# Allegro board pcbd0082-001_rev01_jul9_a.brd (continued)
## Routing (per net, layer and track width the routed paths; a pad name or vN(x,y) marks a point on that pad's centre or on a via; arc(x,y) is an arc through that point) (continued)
NFP_SERDES1_RX2_P: length 55.6
  TOP w0.099: U1.AH26 v2(47.9,52.28)
  07_SIG w0.096: v2(47.9,52.28) 47.9,52.25 47.74,52.09 47.56,52.09 47.51,52.15 47.51,53.62 47.24,53.89 41.47,53.89 41.34,54.01 41.24,54.01 40.81,54.44 38.02,54.44 37.87,54.29 36.82,53.24 33.6,53.24 33.45,53.08 32.34,51.97 30.23,51.97 28.51,50.25 27.64,50.25 27.17,49.77 27.17,47.11 26.85,46.79 26.85,46.25 26.31,45.71 26.11,45.71 26.1,45.7 25.76,45.7 23.8,43.75 23.8,43.58 23.69,43.46 23.69,42.4 21.17,39.87 19.9,39.87 18.99,38.96 18.99,37.73 18.62,37.36 9.78,37.36 9.26,36.84 9.26,35.95 9.62,35.58 10.68,35.58 10.81,35.46 10.85,35.46 v5(10.93,35.37)
  BOTTOM w0.099: J4.136 v5(10.93,35.37)
NFP_SERDES1_RX3_N: length 55
  TOP w0.099: U1.AH27 v8(46.9,52.28)
  07_SIG w0.096: v8(46.9,52.28) 46.5,52.68 46.15,52.68 46.15,52.68 41.44,52.68 41.31,52.81 40.63,52.81 40.53,52.91 38.25,52.91 37.07,51.73 34.28,51.73 33.5,50.95 30.72,50.95 29.07,49.3 29.07,47.05 26.72,44.7 26.52,44.7 26.52,44.7 26.24,44.7 25.33,43.79 25.33,43.17 24.7,42.53 24.7,41.77 22.03,39.1 22.03,38.45 21.79,38.2 21.79,37.62 20.57,36.4 20.57,35.1 20.06,34.59 9.64,34.59 9.52,34.46 9.52,33.76 9.76,33.52 11.22,33.52 11.41,33.34 12.22,33.34 12.43,33.55 12.43,33.87 v5(12.2,34.1)
  BOTTOM w0.099: J4.143 v5(12.2,34.1)
NFP_SERDES1_RX3_P: length 55.1
  TOP w0.099: U1.AJ27 v2(46.9,53.28)
  07_SIG w0.096: v2(46.9,53.28) 46.51,52.89 46.07,52.89 46.06,52.89 41.53,52.89 41.4,53.02 40.78,53.02 40.64,53.17 38.15,53.17 36.97,51.99 34.17,51.99 33.39,51.21 30.61,51.21 28.81,49.41 28.81,47.16 26.62,44.96 26.42,44.96 26.41,44.96 26.14,44.96 25.07,43.89 25.07,43.28 24.44,42.64 24.44,41.87 21.77,39.21 21.77,38.56 21.53,38.31 21.53,37.73 20.31,36.51 20.31,35.2 19.95,34.85 9.54,34.85 9.26,34.57 9.26,33.65 9.65,33.26 11.11,33.26 11.3,33.08 12.1,33.08 12.2,32.97 v5(12.2,32.83)
  BOTTOM w0.099: J4.151 v5(12.2,32.83)
NFP_SERDES1_TX0_N: length 54.8
  TOP w0.099: U1.AK24 v8(49.9,54.28)
  08_SIG w0.096: v5(10.93,50.61) 11.4,51.07 14.07,51.07 14.32,51.32 14.32,52.25 14.41,52.34 16.35,52.34 16.76,52.75 16.76,54.65 16.99,54.88 20.03,54.88 20.52,55.37 20.52,60.45 20.67,60.6 48.52,60.6 49.27,59.85 49.27,57.24 49.29,57.21 49.29,54.89 v8(49.9,54.28)
  BOTTOM w0.099: J4.40 v5(10.93,50.61)
NFP_SERDES1_TX0_P: length 54.9
  TOP w0.099: U1.AL24 v2(49.9,55.28)
  08_SIG w0.096: v5(10.93,51.88) 11.48,51.33 13.96,51.33 14.06,51.43 14.06,52.35 14.3,52.6 16.24,52.6 16.5,52.86 16.5,54.76 16.88,55.14 19.93,55.14 20.26,55.48 20.26,60.56 20.56,60.86 48.63,60.86 49.53,59.96 49.53,57.24 49.51,57.21 49.51,55.11 49.61,55.01 49.79,55.01 49.9,55.11 v2(49.9,55.28)
  BOTTOM w0.099: J4.32 v5(10.93,51.88)
NFP_SERDES1_TX1_N: length 54.9
  TOP w0.099: U1.AL25 v8(48.9,55.28)
  08_SIG w0.096: v8(48.9,55.28) 48.29,55.89 48.29,57.26 48.27,57.29 48.27,59.07 47.49,59.85 21.37,59.85 21.27,59.75 21.27,55.34 21.32,55.3 21.32,52.76 20.87,52.31 18.23,52.31 18.03,52.11 18.03,50.02 17.78,49.77 17.1,49.77 16.85,49.52 16.85,48.9 16.52,48.57 15.54,48.57 15.33,48.57 15.07,48.83 15.07,49.82 14.97,49.92 14.68,49.92 14.58,49.82 14.58,48.83 14.32,48.57 12.71,48.57 v5(12.2,48.07)
  BOTTOM w0.099: J4.55 v5(12.2,48.07)
NFP_SERDES1_TX1_P: length 54.9
  TOP w0.099: U1.AM25 v2(48.9,56.28)
  08_SIG w0.096: v5(12.2,49.34) 12.71,48.83 14.21,48.83 14.32,48.94 14.32,49.93 14.57,50.18 15.08,50.18 15.33,49.93 15.33,48.94 15.43,48.83 16.41,48.83 16.59,49.01 16.59,49.63 17,50.03 17.67,50.03 17.77,50.13 17.77,52.22 18.12,52.57 20.76,52.57 21.06,52.87 21.06,55.19 21.01,55.24 21.01,59.86 21.26,60.11 47.59,60.11 48.53,59.17 48.53,57.27 48.51,57.25 48.51,56.13 48.61,56.03 48.79,56.03 48.9,56.14 v2(48.9,56.28)
  BOTTOM w0.099: J4.47 v5(12.2,49.34)
NFP_SERDES1_TX2_N: length 54.8
  TOP w0.099: U1.AK26 v8(47.9,54.28)
  08_SIG w0.096: v8(47.9,54.28) 47.29,54.89 47.29,57.08 47.27,57.1 47.27,58.45 46.62,59.1 22.87,59.1 22.74,58.97 22.74,58.63 22.49,58.39 22.19,58.39 22.09,58.29 22.09,58 22.19,57.91 22.49,57.91 22.74,57.66 22.74,53.14 20.73,51.14 20.73,50.54 20.11,49.91 19.79,49.91 19.25,49.38 19.25,49.05 18.84,48.64 18.45,48.64 17.98,48.18 17.98,47.78 17.57,47.37 15.7,47.37 15.58,47.25 15.58,45.08 15.23,44.73 14.21,44.73 13.91,45.03 13.91,45.79 13.7,45.99 12.67,45.99 v5(12.2,45.53)
  BOTTOM w0.099: J4.72 v5(12.2,45.53)
NFP_SERDES1_TX2_P: length 54.8
  TOP w0.099: U1.AL26 v2(47.9,55.28)
  08_SIG w0.096: v2(47.9,55.28) 47.9,55.15 47.76,55.01 47.61,55.01 47.51,55.11 47.51,57.08 47.53,57.1 47.53,58.55 46.72,59.36 22.76,59.36 22.48,59.08 22.48,58.74 22.39,58.65 22.08,58.65 21.83,58.4 21.83,57.9 22.08,57.65 22.39,57.65 22.48,57.55 22.48,53.25 20.47,51.25 20.47,50.64 20,50.17 19.68,50.17 18.99,49.48 18.99,49.16 18.73,48.9 18.34,48.9 17.72,48.28 17.72,47.89 17.46,47.63 15.59,47.63 15.32,47.36 15.32,45.19 15.12,44.99 14.32,44.99 14.17,45.14 14.17,45.89 13.81,46.25 12.75,46.25 v5(12.2,46.8)
  BOTTOM w0.099: J4.64 v5(12.2,46.8)
NFP_SERDES1_TX3_N: length 55.3
  TOP w0.099: U1.AL27 v8(46.9,55.28)
  08_SIG w0.096: v8(46.9,55.28) 46.29,55.89 46.29,56.45 46.2,56.54 46.2,57.09 46.18,57.11 46.18,57.86 45.73,58.31 24.24,58.31 23.54,57.61 23.54,56.48 23.65,56.38 25.02,56.38 25.28,56.12 25.28,55.63 25.02,55.37 24.68,55.37 23.65,55.37 23.54,55.26 23.54,54.55 23.65,54.44 24.11,54.44 24.37,54.18 24.37,53.69 24.11,53.43 23.65,53.43 23.54,53.32 23.54,52.41 22.79,51.66 22.79,50.68 20.82,48.71 20.82,48.04 20.02,47.23 19.64,47.23 19.39,46.98 19.39,45.08 19,44.69 17.1,44.69 16.85,44.44 16.85,44.08 16.27,43.49 15.58,43.49 15.47,43.39 15.47,43.21 15.21,42.95 14.72,42.95 14.47,43.21 14.47,43.39 14.36,43.49 12.71,43.49 v5(12.2,42.99)
  BOTTOM w0.099: J4.87 v5(12.2,42.99)
NFP_SERDES1_TX3_P: length 55.2
  TOP w0.099: U1.AM27 v2(46.9,56.28)
  08_SIG w0.096: v5(12.2,44.26) 12.71,43.75 14.47,43.75 14.73,43.49 14.73,43.32 14.83,43.21 15.11,43.21 15.21,43.32 15.21,43.49 15.47,43.75 16.16,43.75 16.59,44.19 16.59,44.55 17,44.95 18.89,44.95 19.13,45.19 19.13,47.09 19.54,47.49 19.91,47.49 20.56,48.14 20.56,48.82 22.53,50.79 22.53,51.77 23.28,52.52 23.28,53.43 23.54,53.69 24,53.69 24.11,53.8 24.11,54.07 24,54.18 23.54,54.18 23.28,54.44 23.28,55.37 23.54,55.63 24.57,55.63 24.92,55.63 25.02,55.73 25.02,56.01 24.92,56.12 23.54,56.12 23.28,56.37 23.28,57.72 24.13,58.57 45.83,58.57 46.44,57.97 46.44,57.11 46.41,57.09 46.41,56.63 46.51,56.53 46.51,56.12 46.6,56.03 46.74,56.03 46.9,56.19 v2(46.9,56.28)
  BOTTOM w0.099: J4.79 v5(12.2,44.26)
NFP_SERDES012_SYSCLK_IN_N: length 13.1
  TOP w0.099: U1.AE26 v2(47.9,49.28) ; R132.2 v7(40.25,51.33)
  04_SIG w0.096: v7(40.25,51.33) 40.25,51.73 40.49,51.98 41.35,51.98 41.65,51.68 45.06,51.68 45.29,51.44 45.29,49.97 45.58,49.68 48.15,49.68 48.25,49.58 48.25,49.4 48.15,49.3 47.92,49.3 v2(47.9,49.28)
  BOTTOM w0.099: v2(47.9,49.28) R322.2
NFP_SERDES012_SYSCLK_IN_P: length 13
  TOP w0.099: U1.AE25 v2(48.9,49.28) ; R133.2 v7(40.25,52.47)
  04_SIG w0.096: v7(40.25,52.47) 40.53,52.19 41.44,52.19 41.74,51.89 45.15,51.89 45.5,51.53 45.5,50.05 45.67,49.89 48.29,49.89 v2(48.9,49.28)
  BOTTOM w0.099: v2(48.9,49.28) R319.2
NFP_SMBUS_ALERT_L: length 12.6
  TOP w0.147: R391.1 21.07,51.29 21.07,50.32 22.72,48.66 24.5,48.66 24.75,48.92 24.75,51.59 25.26,52.09 v4(25.26,52.47) 25.26,53.11 25.26,53.11 U20.4
  BOTTOM w0.147: R379.1 25.26,53.83 v4(25.26,52.47)
NFP_SMBUS_SCL: length 15.5
  TOP w0.147: v4(27.39,57.43) 27.22,57.25 U20.9 ; R389.1 v5(17.51,58.57)
  07_SIG w0.121: v5(17.51,58.57) 17.51,58.85 18.24,59.57 20.07,59.57 20.13,59.51 23.88,59.51 24.06,59.33 25.49,59.33 v4(27.39,57.43)
  BOTTOM w0.147: R370.1 27.39,56.55 v4(27.39,57.43)
NFP_SMBUS_SDA: length 5.9
  TOP w0.147: U20.7 26.76,52.95 R382.1 v4(27.39,52.47) 28.05,52.47 29.32,51.2 R351.1
  BOTTOM w0.147: v4(27.39,52.47) 27.39,53.35 R369.1
NFP_SPI2_CS: length 16.5
  TOP w0.127: v3(32.63,38.56) 32.21,38.09 32.21,37.54 32.32,37.43 32.32,37.42 32.91,36.83 U2.P11
  TOP w0.132: U1.W31 v2(42.9,43.28)
  TOP w0.147: v3(32.63,38.56) v1(32.63,39.39)
  03_SIG w0.121: v2(42.9,43.28) 42.9,42.94 42.31,42.35 42.31,41.97 42.02,41.68 40.63,41.68 37.96,39.01 33.01,39.01 32.63,38.63 v3(32.63,38.56)
NFP_SPI2_MISO: length 11.8
  TOP w0.132: U1.V31 v8(42.9,42.28)
  02_GND w0.127: U2.N4 35.98,36.71 v3(35.98,37.72)
  03_SIG w0.121: v3(35.98,37.72) 35.98,37.7 35.99,37.69 36.13,37.69 36.56,38.12 37.96,38.12 38.23,38.39 38.23,38.51 38.47,38.76 39.74,38.76 40.11,39.13 40.74,39.13 42.41,40.79 42.41,41.43 42.9,41.92 v8(42.9,42.28)
NFP_SPI2_MOSI: length 16.3
  TOP w0.127: U2.P13 31.37,37.32 31.37,38.06 v3(31.81,38.56)
  07_SIG w0.121: v3(31.81,38.56) 32.65,39.39 39.61,39.39 40.21,39.99 43.46,39.99 43.9,39.55 v2(43.9,39.28)
  BOTTOM w0.147: R203.2 43.98,39.36 v2(43.9,39.28)
NFP_SPI2_SCK: length 13.1
  TOP w0.127: U2.M4 36.36,35.78 36.04,35.46 35.78,35.46 v3(35.5,35.18)
  07_SIG w0.121: v3(35.5,35.18) 35.83,35.18 36.19,34.81 38.31,34.81 38.43,34.68 39.62,34.68 40.5,33.81 45.38,33.81 v2(45.9,33.28)
  BOTTOM w0.147: R199.2 v2(45.9,33.28)
NFP_SRESET_L: length 17.9
  TOP w0.132: U1.M29 v2(44.9,35.28)
  02_GND w0.127: U2.N13 31.91,37.6 v3(31.79,37.72)
  07_SIG w0.121: v2(44.9,35.28) 44.87,35.28 44.44,35.71 43.9,35.71 43.5,36.12 43.5,36.27 43.04,36.73 41.52,36.73 41.07,36.28 33.23,36.28 v3(31.79,37.72)
  BOTTOM w0.127: R57.1 30.98,36.9 v3(31.79,37.72)
NFP_UART_SR_RX: length 52.2
  TOP w0.132: U1.N31 v2(42.9,36.28)
  04_SIG w0.121: v4(48.25,12.6) 47.61,11.96 46.08,11.96 46.02,12.02 44.61,12.02 44.17,11.58 43.17,11.58 42.53,12.22 39.61,12.22 38.85,12.98 38.85,13.74 38.09,14.5 34.33,14.5 33.19,13.36 30.92,13.36 30.66,13.62 30.66,13.85 30.01,14.5 28.81,14.5 v4(28.56,14.25)
  08_SIG w0.121: v4(48.25,12.6) 47.49,13.36 43.8,13.36 42.85,14.31 42.85,22.95 43.42,23.52 43.42,35.76 v2(42.9,36.28)
NFP_UART_SR_TX: length 45.8
  07_SIG w0.121: v5(28.56,12.91) 28.56,12.85 29.58,11.83 31.11,11.83 32.32,10.63 32.68,10.63 33.3,11.25 35.42,11.25 35.8,11.63 37.02,11.63 37.65,11.01 38.52,11.01 38.89,10.64 38.9,10.63 40.05,10.63 40.67,10 41.71,10 41.97,9.74 42.85,9.74 43.75,10.64 45.52,10.64 46.34,11.46 v4(46.34,12.6)
  08_SIG w0.121: v5(28.56,12.91) 28.5,12.98 27.55,12.98 26.78,13.74 26.78,18.24 27.93,19.38 27.93,21.06 28.3,21.43 28.3,23.79 28.18,23.91 28.18,27.21 28.24,27.27 28.24,27.64 28.05,27.83 28.05,29.23 27.55,29.74 26.59,29.74 v4(25.78,30.55)
  BOTTOM w0.147: v4(25.78,30.55) 26.11,30.88 R200.2 ; J5.26 v5(28.56,12.91)
NFP_VDD_CORE_IMON: length 4.2
  TOP w0.147: U10.8 29.98,19.47 29.83,19.33 v4(29.49,19.33) C125.2
  BOTTOM w0.147: v4(29.49,19.33) 28.94,19.33 TP38.1
NFP_VDD_CORE_ISEN1_N: length 34.3
  07_SIG w0.254: v4(39.9,20.71) 40.23,20.71 41.26,21.74 44.52,21.74 45.66,22.88 47,22.88 47.94,23.81 58,23.81 58.38,23.43 68.19,23.43 68.44,23.18 68.44,22.56 68.75,22.25 69.2,22.25 69.46,21.99 69.46,21.74 69.2,21.49 68.2,21.49 67.77,21.92 v4(67.77,21.99)
NFP_VDD_CORE_ISEN1_P: length 37
  TOP w0.254: v5(70.54,22.57) 70.47,22.5 70.47,22.38 70.38,22.29 R171.2 ; v4(39.9,19.7) R325.2
  07_SIG w0.254: v4(39.9,19.7) 39.4,20.29 39.4,20.92 39.69,21.22 40.2,21.22 41.1,22.12 44.36,22.12 45.5,23.26 46.85,23.26 47.43,23.84 47.43,24.48 47.7,24.75 48.72,24.75 48.76,24.79 57.56,24.79 58.53,23.81 68.4,23.81 68.69,23.52 69.58,23.52 v5(70.54,22.57)
NFP_VDD_CORE_ISEN2_N: length 22.8
  07_SIG w0.254: v4(57.18,21.87) 55.28,21.87 54.13,23.01 50.63,23.01 49.61,21.99 47.11,21.99 46.9,21.78 46.73,21.78 46.35,21.4 46.32,21.4 45.9,20.98 44.02,20.98 43.52,20.48 41.71,20.48 38.98,17.74 38.98,17.01 39.4,16.58 39.59,16.58 v4(39.88,16.28)
NFP_VDD_CORE_ISEN2_P: length 19.6
  TOP w0.254: v4(39.88,17.17) R324.2
  07_SIG w0.254: v4(54.56,21.87) 53.84,22.59 53.84,22.63 50.79,22.63 49.77,21.61 47.27,21.61 47.05,21.4 46.89,21.4 46.51,21.02 46.47,21.02 46.06,20.6 44.18,20.6 43.68,20.1 41.87,20.1 39.36,17.58 39.36,17.17 39.56,16.97 39.67,16.97 v4(39.88,17.17)
NFP_VDD_CORE_SENSE_VDD: length 52.9
  TOP w0.254: R313.2 v5(34.53,13.1) ; v5(34.53,13.1) v1(35.07,12.57) ; v5(34.53,13.1) R182.2 ; U1.AC25 v2(48.9,47.28)
  07_SIG w0.254: v2(48.9,47.28) 48.37,46.75 48.37,27.96 48.13,27.72 48.09,27.75 47.7,27.75 47.66,27.71 47.1,27.71 46.72,27.33 46.72,26.44 46.04,25.75 41.7,25.75 41.43,25.48 41.43,25.43 41.04,25.04 39.48,25.04 38.6,24.16 38.28,24.16 38.22,24.11 36.9,24.11 36.11,23.32 36.11,19.22 35.43,18.55 34.23,18.55 32.81,17.13 32.81,17.11 v5(32.44,16.74)
  BOTTOM w0.254: v2(48.9,47.28) 49.4,47.78 R286.1 ; v5(34.53,13.1) 33.39,13.1 31.99,14.5 31.99,16.29 v5(32.44,16.74)
NFP_VDD_CORE_SENSE_VSS: length 53.2
  TOP w0.254: U10.13 33.03,17.08 33.19,16.91 v5(33.31,16.91) ; C125.1 R323.2 28.65,18.57 v4(28.44,18.35) ; U1.AC24 v2(49.9,47.28)
  07_SIG w0.254: v5(33.31,16.91) 33.27,16.93 33.4,16.93 34.64,18.17 35.59,18.17 36.49,19.07 36.49,23.16 37.06,23.73 38.38,23.73 38.43,23.78 38.86,23.78 39.17,24.09 39.17,24.11 39.46,24.41 39.48,24.41 39.74,24.66 41.26,24.66 41.41,24.81 43.09,24.81 43.65,25.37 46.19,25.37 47.63,26.81 48.09,26.81 48.37,27.09 48.37,27.42 48.76,27.81 49.09,27.81 49.39,28.11 49.39,46.76 49.9,47.27 v2(49.9,47.28)
  BOTTOM w0.254: v4(28.44,18.35) 28.44,17.74 29.13,17.04 30.88,17.04 31.08,17.24 31.51,17.24 31.56,17.3 32.93,17.3 v5(33.31,16.91) ; v2(49.9,47.28) R285.2
NFP_VDD_CORE_TCOMPA: length 35.5
  TOP w0.147: v4(38.98,15.35) R327.2 38.05,15.39 C34.2 C35.2 36.73,16.79 36.02,16.79 35.53,17.28 U10.18
  04_SIG w0.121: v4(65.18,12.47) 64.62,12.47 64.5,12.35 64.5,12.13 64.5,12.12 64.5,11.48 64.1,11.08 62.31,11.08 62.12,10.89 60.03,10.89 58.19,12.73 49.14,12.73 48.71,13.17 45.86,13.17 45.43,12.73 40.54,12.73 39.44,13.82 39.44,14.8 39.44,14.92 v4(38.98,15.35)
NFP_VDD_CORE_TCOMPB: length 32.8
  TOP w0.147: v4(40.12,15.39) 40.12,14.88 39.65,14.41 R329.2 38.89,14.5 R13.1
  04_SIG w0.121: v4(40.12,15.39) 39.69,14.93 39.69,14.81 39.69,13.93 40.64,12.98 45.33,12.98 45.76,13.41 48.81,13.41 49.24,12.98 58.29,12.98 58.56,12.71 60.13,11.14 62.02,11.14 62.21,11.33 64,11.33 64.25,11.58 64.25,12.23 64.25,12.23 64.25,12.35 64.13,12.47 v4(63.58,12.47)
NWK0_I2C_SCL: length 17
  08_SIG w0.121: v5(10.93,31.56) 11.16,31.79 11.16,33.22 10.73,33.66 9.79,33.66 v7(6.72,36.73) 5.96,37.49 v4(5.96,42.7)
  BOTTOM w0.147: R377.1 5.96,41.97 v4(5.96,42.7) 5.96,43.33 5.95,43.33 U21.4
  BOTTOM w0.254: J4.160 v5(10.93,31.56)
NWK0_I2C_SDA: length 16.9
  08_SIG w0.121: v4(3.82,42.7) 5.19,41.32 v7(5.19,37.36) 5.19,37.18 9.55,32.83 10.62,32.83 v5(10.66,32.79)
  BOTTOM w0.147: R373.1 3.97,42 R386.1 4.45,43.17 U21.7
  BOTTOM w0.254: v5(10.66,32.79) 10.97,32.79 J4.152
NWK0_LED_ACT_G_L: length 39.8
  TOP w0.127: v3(34.51,32.76) 34.92,32.35 35.49,32.35 35.74,32.1 35.74,31.87 36.02,31.6 36.09,31.6 U2.C4
  03_SIG w0.121: v5(13.47,41.72) 13.96,41.24 13.96,35.33 14.39,34.89 23.66,34.89 24.75,33.81 24.75,30.96 25.6,30.11 25.65,30.11 25.9,29.87 28.04,29.87 28.52,30.35 28.66,30.35 29.69,31.38 29.69,31.4 29.92,31.63 29.94,31.63 29.96,31.65 32.63,31.65 33.3,32.32 34.06,32.32 v3(34.51,32.76)
  BOTTOM w0.147: v1(37.71,31.14) 37.26,31.59 36.01,31.59 35.76,31.84 35.76,32.09 35.09,32.76 v3(34.51,32.76)
  BOTTOM w0.254: J4.94 v5(13.47,41.72)
NWK0_LED_LINK_G_L: length 40.4
  02_GND w0.121: U2.B3 36.91,29.7 37.58,29.03 37.58,28.47 v3(37.71,28.34)
  03_SIG w0.121: v3(37.71,28.34) 37.71,28.9 35.82,30.79 29.87,30.79 29.11,30.03 29.11,29.76 28.86,29.52 25.87,29.52 25.51,29.87 25.13,29.87 24.3,30.7 24.3,33.75 23.42,34.63 22.54,34.63 22.45,34.54 13.22,34.54 12.94,34.82 12.94,39.39 13.47,39.93 v5(13.47,40.45)
  BOTTOM w0.254: J4.102 v5(13.47,40.45)
NWK0_MOD_PRES_L: length 25.1
  02_GND w0.121: v3(33.69,32.74) 34.11,32.32 34.11,31.56 34.4,31.27 34.42,31.27 U2.B7
  04_SIG w0.121: v3(33.69,32.74) 31.31,32.74 30.59,32.03 28.94,32.03 28.46,31.54 26.14,31.54 25.26,30.66 23.68,30.66 23.45,30.88 21.83,30.88 21.45,30.5 14.53,30.5 v5(13.47,31.56)
  BOTTOM w0.254: J4.158 v5(13.47,31.56)
NWK1_I2C_SCL: length 38
  08_SIG w0.121: v6(19.82,34.1) 20.43,33.49 20.43,30.76 19.93,30.25 11.42,30.25 3.29,38.38 3.29,43.84 3.82,44.37 v4(3.82,47.65)
  BOTTOM w0.147: R374.1 v4(3.82,47.65) 4,47.47 U21.9
  BOTTOM w0.254: J4.137 v6(19.82,34.1)
NWK1_I2C_SDA: length 35.9
  08_SIG w0.121: v4(5.96,47.65) 5.58,47.27 5.58,45.11 7.61,43.08 7.61,38.07 8.98,36.7 8.98,35.56 10,34.54 11.5,34.54 11.76,34.28 11.76,31.3 12.05,31.01 19.04,31.01 19.29,31.27 19.29,34.19 19.38,34.28 19.38,34.28 19.82,34.72 v6(19.82,35.37)
  BOTTOM w0.147: R378.1 5.61,48.5 5.96,48.16 v4(5.96,47.65) 5.45,47.14 U21.12
  BOTTOM w0.254: J4.129 v6(19.82,35.37)
NWK1_LED_ACT_G_L: length 31.4
  TOP w0.127: v3(30.95,29.08) 31.91,30.01 U2.A13
  08_SIG w0.121: v5(14.74,39.18) 14.8,39.18 14.8,39.12 15.35,38.57 15.35,37.74 15.63,37.47 20.2,37.47 21.14,36.53 21.14,35.39 21.45,35.08 22.28,35.08 22.33,35.12 23.11,35.12 23.16,35.08 24.24,35.08 26.21,37.04 28.18,37.04 28.63,37.49 29.58,37.49 30.02,37.04 30.28,37.04 31.1,36.22 31.1,29.87 30.98,29.74 v3(30.95,29.08)
  BOTTOM w0.147: v3(30.95,29.08) 30.95,29.59 v1(31.23,29.87)
  BOTTOM w0.254: J4.109 v5(14.74,39.18)
NWK1_LED_LINK_G_L: length 30.7
  TOP w0.147: v3(37.66,37.72) 37.68,37.72 38.09,38.12 38.09,38.63 38.34,38.89 v1(39.48,38.89)
  02_GND w0.127: v3(37.66,37.72) 37.66,37.02 U2.N3
  03_SIG w0.121: v3(37.66,37.72) 37.37,37.72 36.98,37.33 30.06,37.33 28.95,36.22 28.13,36.22 28.07,36.27 26.65,36.27 26.59,36.22 26.08,36.22 25.01,35.14 20.75,35.14 20.05,35.84 19.55,35.84 19.14,36.25 19.14,36.76 18.81,37.08 15.57,37.08 v5(14.74,37.91)
  BOTTOM w0.254: J4.117 v5(14.74,37.91)
NWK1_MOD_PRES_L: length 54.4
  02_GND w0.127: v3(30.09,30.4) 31.03,30.4 U2.C13
  08_SIG w0.121: v5(13.47,54.42) 13.47,54.41 12.69,53.62 10.53,53.62 10.33,53.42 10.33,39.13 11.67,37.8 11.67,37.49 11.93,37.23 12.81,37.23 12.98,37.07 12.98,35.16 13.27,34.87 13.45,34.69 16.12,34.69 16.84,35.42 16.84,35.55 18.4,37.11 20.05,37.11 20.82,36.35 20.82,35.2 21.32,34.69 22.25,34.69 22.43,34.88 23.01,34.88 23.19,34.69 24.5,34.69 26.4,36.6 30.21,36.6 30.85,35.96 30.85,31.16 v3(30.09,30.4)
  BOTTOM w0.148: J4.14 v5(13.47,54.42)
PCIE0_REFCLK_N: length 63.9
  TOP w0.099: v8(60.9,49.28) U1.AE14
  04_SIG w0.096: v8(60.9,49.28) 61.29,49.68 61.29,50.53 61.65,50.89 62.06,50.89 62.29,51.12 62.29,55.72 62.27,55.74 62.27,55.99 61.58,56.68 57.74,56.68 57.34,56.28 56.63,56.28 56.23,56.68 55.74,56.68 55.5,56.45 55.5,56.44 55.39,56.33 54.68,56.33 54.33,56.68 53.71,56.68 53.31,56.28 52.58,56.28 52.18,56.68 50.79,56.68 50.17,57.29 32.96,57.29 32.42,57.83 29.38,57.83 28.13,56.58 23.77,56.58 23.16,55.97 21.26,55.97 20.17,54.88 11.77,54.88 11.56,54.68 11.56,54.36 11.67,54.25 12.04,54.25 v5(12.2,54.42)
  BOTTOM w0.099: J4.16 v5(12.2,54.42)
PCIE0_REFCLK_P: length 64.1
  TOP w0.099: v8(61.9,49.28) U1.AE13
  04_SIG w0.096: v5(10.93,54.42) 11.66,55.14 20.07,55.14 21.16,56.23 23.05,56.23 23.66,56.84 28.02,56.84 29.27,58.09 32.53,58.09 33.07,57.55 50.28,57.55 50.89,56.94 52.29,56.94 52.69,56.54 53.2,56.54 53.6,56.94 54.44,56.94 54.79,56.59 55.28,56.59 55.63,56.94 56.34,56.94 56.74,56.55 57.23,56.55 57.63,56.94 61.69,56.94 62.53,56.1 62.53,55.65 62.53,55.65 62.53,55.56 62.5,55.54 62.5,51.03 62.15,50.67 61.74,50.67 61.51,50.44 61.51,49.68 v8(61.9,49.28)
  BOTTOM w0.099: J4.8 v5(10.93,54.42)
PCIE0_RST_L: length 56.1
  TOP w0.132: U1.P30 v2(43.9,37.28)
  TOP w0.147: v6(18.55,55.69) 19.02,56.16 20.18,56.16 20.43,56.41 R73.2
  02_GND w0.127: v3(38.62,36.7) 38.33,36.7 U2.M2
  04_SIG w0.121: v5(21.58,35.58) 22.28,34.88 22.28,34 22.54,33.75 24.82,33.75 27.29,36.22 29.45,36.22 29.9,35.77 30.2,35.77 30.26,35.71 35.83,35.71 36.82,36.7 v3(38.62,36.7)
  07_SIG w0.121: v6(18.55,55.69) 18.55,55.68 18.02,55.14 18.02,49.17 18.68,48.51 18.74,48.51 19.73,47.52 20.82,47.52 v5(22.34,46) ; v3(38.62,36.7) 39.15,37.23 40.16,37.23 40.17,37.25 40.5,37.25 40.99,37.74 43.17,37.74 43.63,37.28 v2(43.9,37.28)
  08_SIG w0.121: v5(22.34,46) 21.45,46 21.07,45.62 21.07,43.46 21.83,42.7 21.83,35.84 v5(21.58,35.58)
  BOTTOM w0.254: J4.2 v6(18.55,55.69)
PCIE0_WAKE_L: length 8.6
  TOP w0.147: v1(15.23,59.08) 13.2,59.08 13.14,59.03 13.13,59.03 12.87,58.76 12.87,57.46 R367.2 R368.2 14.97,56.51 15.2,56.51 v5(16.01,55.69)
  BOTTOM w0.254: J4.4 v5(16.01,55.69)
PGRM_JTAG_TCK: length 56.4
  TOP w0.132: U1.AB32 v2(41.9,46.28)
  03_SIG w0.121: v7(25.39,46.89) 25.39,46.76 25.39,46.76 25.39,46.63 22.75,43.99 22.75,43.66 22.47,43.38 22.47,40.92 21.55,40.01 19.64,40.01 19.29,40.36 19.29,40.92 18.4,41.81 18.4,42.44 18.11,42.73 18.11,44.05 17.47,44.7 17.03,44.7 16.75,44.98 16.75,47.01 16.31,47.46 15.16,47.46 14.97,47.65 14.97,48.16 14.62,48.51 13.1,48.51 12.65,48.96 12.65,49.52 12.39,49.78 12.02,49.78 11.76,49.52 11.76,49.39 10.88,48.51 9.03,48.51 8.75,48.79 8.75,48.79 v5(7.1,50.44)
  04_SIG w0.121: v2(41.9,46.28) 40.89,47.29 40.89,47.89 40.17,48.6 40.06,48.6 39.8,48.86 39.8,48.94 39.13,49.61 39.13,50.37 38.82,50.68 37.73,50.68 36.9,49.85 35.5,49.85 35.45,49.8 33.86,49.8 33.63,49.56 32.96,49.56 31.98,48.58 31.98,48.34 31.92,48.28 31.92,48.23 31.67,47.97 26.72,47.97 25.64,46.89 v7(25.39,46.89)
  BOTTOM w0.147: TP27.1 7.48,50.82 v5(7.1,50.44) ; R45.1 U1.AB32 v2(41.9,46.28)
PGRM_JTAG_TDI: length 52.4
  TOP w0.132: U1.AD32 v2(41.9,48.28)
  03_SIG w0.121: v5(9.79,49.34) 10.62,50.17 12.58,50.17 13.03,49.72 13.03,49.16 13.29,48.9 16.39,48.9 16.62,48.66 16.62,48.08 17.73,46.98 17.73,45.4 18.43,44.7 18.74,44.7 19,44.44 19,42.57 19.38,42.19 21.58,42.19 21.96,42.57 21.96,43.58 22.24,43.87 22.24,44.2 24.89,46.84 24.89,47.09 25.18,47.39 25.51,47.39 26.78,48.66 v5(28.18,48.66)
  04_SIG w0.121: v2(41.9,48.28) 41.14,49.05 41.14,50.44 40.95,50.63 39.93,50.63 39.74,50.82 39.74,51.4 39.1,52.03 38.03,52.03 36.69,50.7 34.22,50.7 34.1,50.57 30.09,50.57 v5(28.18,48.66)
  BOTTOM w0.147: R44.2 27.93,48.41 v5(28.18,48.66) 28.44,48.41 R148.1 ; v1(6.54,49.75) 6.65,49.75 6.85,49.55 7.86,49.55 8.29,49.12 TP28.1 9.58,49.12 v5(9.79,49.34)
PGRM_JTAG_TDO: length 46.4
  07_SIG w0.121: v4(3.82,51.75) 3.84,51.75 5.32,53.24 7.23,53.24 7.61,53.62 7.61,54.13 7.1,54.63 7.1,57.17 10.5,60.57 26.31,60.57 28.82,58.06 28.82,54.38 v7(28.05,53.62)
  08_SIG w0.121: v4(29.87,48.41) 28.69,49.59 28.69,52.98 v7(28.05,53.62)
  BOTTOM w0.147: TP29.1 4.29,52.22 v4(3.82,51.75) ; R43.2 v4(29.87,48.41)
PGRM_JTAG_TMS: length 54.6
  TOP w0.132: U1.AC31 v2(42.9,47.28)
  03_SIG w0.121: v4(3.82,50.48) 5.51,48.79 5.51,47.39 8.44,44.47 10.4,44.47 10.63,44.7 13.66,44.7 13.92,44.44 13.92,44.26 14.36,43.82 15.81,43.82 16.46,43.17 16.46,42.48 16.84,42.1 16.84,41.54 17.1,41.28 17.15,41.28 19.17,39.26 19.17,39.19 20.01,38.35 20.27,38.09 20.27,37.53 20.69,37.11 22.72,37.11 25.51,39.9 27.29,39.9 27.99,40.6 27.99,40.85 34.6,47.46 37.89,47.46 38.6,46.76 42.02,46.76 42.55,47.28 v2(42.9,47.28)
  BOTTOM w0.147: v4(3.82,50.48) 4.04,50.7 TP30.1 ; v2(42.9,47.28) R42.2
PGRM_JTAG_TRST_L: length 59.7
  TOP w0.132: U1.AB31 v2(42.9,46.28)
  07_SIG w0.121: v5(7.1,53.74) 6.72,54.13 6.72,57.43 10.15,60.86 26.78,60.86 29.95,57.69 31.85,57.69 33.19,56.35 34.33,56.35 35.22,57.23 36.12,57.23 36.93,56.43 v7(40.75,56.43)
  08_SIG w0.121: v7(40.75,56.43) 41.32,56.43 42.3,55.45 42.3,55.12 42.79,54.63 42.79,54.25 43.3,53.74 43.3,53.31 43.73,52.88 43.87,52.88 44.44,52.32 44.44,50.06 43.42,49.05 43.42,46.76 42.94,46.28 v2(42.9,46.28)
  BOTTOM w0.147: v5(7.1,53.74) 7.99,52.86 8.22,52.86 8.37,52.71 TP26.1 ; R41.2 43.4,46.78 v2(42.9,46.28) U1.AB31 R46.1
PSU_I2C_SCL: length 93.8
  TOP w0.127: U2.C8 34.41,31.73 v3(34.51,31.93)
  TOP w0.147: v4(30.47,20.85) 30.59,20.97 U10.5 ; v5(23.36,21.99) 22.72,21.99 22.6,21.88 22.6,21.87 22.27,21.54 21.9,21.54 21.57,21.87 20.43,21.87 20.29,22.01 U9.15 ; TP15.1 5.32,23.26 v7(5.58,23.52) R131.1
  07_SIG w0.121: v7(5.58,23.52) 6.08,23.01 6.59,23.01 6.6,23.02 6.67,23.02 6.91,23.26 6.91,23.7 7.17,23.96 7.23,23.96 7.56,24.29 10.48,24.29 10.6,24.41 11.34,24.41 12.43,25.5 12.43,25.55 12.94,26.06 18.91,26.06 19.42,25.55 19.42,24.79 20.18,24.03 20.18,21.41 20.63,20.95 21.04,20.95 21.45,21.36 21.45,21.41 21.57,21.53 21.57,22.24 21.83,22.5 22.47,22.5 22.97,21.99 v5(23.36,21.99) 23.36,22.88 23.8,23.33 23.8,23.77 24.19,24.15 25.27,24.15 25.58,23.84 25.58,23.2 25.9,22.88 25.9,21.49 27.42,19.96 29.58,19.96 29.78,20.16 29.88,20.16 30.43,20.72 30.43,20.82 v4(30.47,20.85) 31.23,21.61 31.23,22.76 30.91,23.08 30.91,23.74 31.45,24.28 32.12,24.28 33.77,25.93 33.77,27.09 33.71,27.15 33.71,27.51 33.77,27.57 33.77,28.98 33.83,29.05 33.83,30.72 34.51,31.39 v3(34.51,31.93)
  08_SIG w0.121: v3(34.51,31.93) 34.11,32.32 34.11,32.87 33.86,33.13 33.68,33.13 33.45,33.36 33.45,34.53 33.19,34.79 32.79,34.79 32.63,34.95 32.63,36.09 33.9,37.36 33.9,39.01 31.48,41.43 31.48,46.25 30.62,47.12 v5(29.93,47.28) ; v5(23.36,21.99) 22.85,22.5 21.07,22.5 19.55,20.98 19.55,20.47 17.64,18.57 17.64,12.09 17.13,11.58 v4(17.13,10.12)
PSU_I2C_SDA: length 86.1
  TOP w0.147: R130.1 v5(6.46,23.52) 6.46,22.88 7.23,22.12 TP16.1 ; U10.4 30.73,21.47 v5(30.34,21.87) ; v7(20.82,21.39) 20.47,21.39 20.29,21.21 U9.13 ; v5(28.69,46) R139.2
  02_GND w0.121: U2.B8 33.75,30.12 33.62,30.12 v3(32.58,29.08)
  07_SIG w0.121: v3(32.58,29.08) 32.81,28.84 32.81,25.76 31.67,24.61 31.14,24.61 30.88,24.35 30.79,24.35 29.96,23.52 29.96,22.25 v5(30.34,21.87) 30.03,21.55 30.03,21.12 29.93,21.02 29.93,20.92 29.67,20.66 29.57,20.66 29.5,20.6 28.09,20.6 27.86,20.83 27.86,21.42 27.6,21.67 27.24,21.67 26.98,21.42 26.68,21.42 26.46,21.63 26.46,23.89 26.41,23.95 26.41,24.27 26.02,24.66 22.59,24.66 21.89,23.96 21.89,23.55 21.07,22.73 21.07,21.65 v7(20.82,21.39) 20.68,21.53 20.68,24.74 20.56,24.86 20.56,25.68 19.23,27.01 12.49,27.01 10.27,24.79 7.35,24.79 6.46,23.9 v5(6.46,23.52)
  08_SIG w0.121: v4(18.4,10.12) 18.4,11.45 19.16,12.22 19.16,15.52 19.67,16.03 19.67,17.93 19.16,18.44 19.16,19.2 20.82,20.85 v7(20.82,21.39) ; v5(28.69,46) 29.32,45.36 29.32,40.49 31.65,38.16 31.95,38.16 32.18,37.94 32.18,37.56 31.99,37.37 31.99,32.41 32.58,31.82 v3(32.58,29.08)
PWR_GOOD_LED_L: length 133.7
  TOP w0.127: v3(29.27,32.79) 29.69,32.37 31,32.37 U2.F14
  TOP w0.147: TP14.1 2.78,21.36 v5(2.27,21.36)
  03_SIG w0.121: v5(10.66,9.99) 10.97,10.31 15.42,10.31 v4(15.86,9.87)
  04_SIG w0.121: v3(29.27,32.79) 29.69,33.21 29.69,33.82 29.45,34.06 27.8,34.06 26.34,32.6 22.77,32.6 22.52,32.35 22.16,32.35 21.91,32.6 21.14,32.6 20.43,33.3 15.86,33.3 15.57,33.01 15.57,33.01 14.95,32.39 11.14,32.39 10.49,31.74 10.49,31.62 7.28,28.41 6.67,28.41 4.24,25.99 4.24,25.87 4.24,25.87 4.24,23.34 4.43,23.14 4.43,23.13 4.55,23.01 9.13,23.01 11.16,20.98 11.54,20.98 12.31,20.22 12.31,19.84 12.05,19.58 11.29,19.58 10.78,20.09 10.78,20.22 10.27,20.72 9.89,20.72 9.51,20.34 9.51,11.14 v5(10.66,9.99)
  07_SIG w0.121: v5(9.26,57.43) 9.26,51.2 6.59,48.54 3.67,48.54 2.65,47.52 2.65,29.49 v7(3.16,28.98) 2.65,28.47 2.65,22.63 2.27,22.25 v5(2.27,21.36) 8.12,21.36 9.64,19.84 9.64,12.98 11.54,11.07 14.59,11.07 15.8,9.87 v4(15.86,9.87)
  BOTTOM w0.147: R277.1 7.82,55.1 9.26,56.54 v5(9.26,57.43)
SMBUS_ALERT_L: length 15
  TOP w0.147: v5(14.74,55.69) 14.08,55.03 14.08,54.13 14.33,53.88 16.45,53.88 16.62,54.05 16.62,54.76 16.88,55.01 v1(20.79,55.01) 20.94,54.87 20.94,54.63 21.58,54 21.58,52.77 R391.2 21.18,52.64 21.02,52.47 21.02,51.88 R392.2
  BOTTOM w0.254: J4.6 v5(14.74,55.69)
SMBUS_SCL: length 9.7
  TOP w0.147: v1(18.28,59.59) 18.2,59.51 18.2,57.63 18.33,57.5 18.33,57.5 18.45,57.38 18.45,57.38 18.78,57.05 R390.2 18.31,56.54 17.98,56.54 R389.2 17.47,57.01 16.62,56.16 16.62,55.4 16.24,55.01 15.34,55.01 v5(14.74,54.42)
  BOTTOM w0.132: J4.13 v5(14.74,54.42)
SMBUS_SDA: length 22.4
  TOP w0.147: R351.2 29.32,48.66 28.69,48.03 22.97,48.03 v1(21.96,47.01) 21.92,47.05 R350.2 20.82,49.17 20.05,49.93 19.55,49.93 19.29,50.19 19.29,52.22 19.04,52.47 15.48,52.47 14.81,53.15 v5(14.74,53.15)
  BOTTOM w0.254: J4.21 v5(14.74,53.15)
VR_OD1_L: length 37.7
  TOP w0.147: U10.21 37.96,17.74 37.96,17.47 38,17.42 v7(38,17.4)
  07_SIG w0.121: v5(65.39,21.61) 59.17,21.61 58.03,20.47 57.26,20.47 56.91,20.11 56.91,18.59 55.99,17.68 55.99,17.55 53.33,14.88 47.49,14.88 46.54,15.83 39.49,15.83 39.48,15.84 38.78,15.84 38.53,16.09 38.53,16.4 38,16.92 v7(38,17.4)
  BOTTOM w0.147: R170.1 65.39,24.78 65.39,24.15 65.6,23.94 65.61,23.94 65.72,23.84 65.72,23.84 65.96,23.6 65.96,23.02 65.77,22.84 65.77,21.99 v5(65.39,21.61)
VR_ODN_L: length 15.5
  TOP w0.147: U10.20 v5(37.2,17.78)
  07_SIG w0.121: v7(45.96,23.9) 45.33,23.9 44.56,23.14 43.29,23.14 43.17,23.01 39.31,23.01 39.25,23.07 38.88,23.07 38.62,22.81 38.62,22.79 38.35,22.52 37.85,22.52 37.2,21.87 v5(37.2,17.78)
  BOTTOM w0.147: R169.1 45.92,23.94 v7(45.96,23.9)

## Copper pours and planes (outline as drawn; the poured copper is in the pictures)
GND on TOP (solid shape): 19.16,16.15 18.28,16.15 18.28,16.92 18.34,16.98 18.34,18.31 19.16,18.31
GND on TOP (solid shape): 23.23,18.31 23.74,18.31 23.74,17.55 21.67,17.55 21.67,18.4 21.96,18.69 22.85,18.69
GND on TOP (solid shape): 14.08,19.07 14.02,19 14.02,17.55 12.81,17.55 12.56,17.8 11.8,17.8 11.8,18.95 13.07,18.95 13.83,19.71 14.08,19.71
GND on TOP (solid shape): 14.53,24.09 14.21,23.77 14.08,23.77 13.56,24.29 13.56,24.34 13.51,24.34 13.07,24.79 12.56,24.79 12.56,25.8 14.53,25.8
GND on TOP (solid shape): 21.83,25.8 21.83,24.92 21.07,24.92 20.56,24.41 20.56,24.15 19.93,24.15 19.93,24.66 19.86,24.73 19.86,25.8
GND on TOP (solid shape): 17.58,22.5 17.74,22.48 17.9,22.5 17.91,22.51 18.47,22.51 18.52,22.49 18.52,21.7 19.2,21.7 19.2,21.52 18.52,21.52 18.52,20.85 18.49,20.78 18.42,20.75 18.34,20.74 18.25,20.72 17.03,20.72 16.93,20.74 16.84,20.75 16.77,20.78 16.74,20.85 16.74,21.52 16.08,21.52 16.08,21.7 16.74,21.7 16.74,22.12 16.75,22.13 16.77,22.25 16.77,22.36 16.8,22.44 16.87,22.48 16.94,22.49 17.01,22.51 17.57,22.51
GND on BOTTOM (solid shape): outline of 197 points within 49.99,6.63 60.82,18.44
GND on BOTTOM (solid shape): outline of 942 points within 62.22,4.98 87.87,18.44
GND on TOP: 82.41,10.06 82.41,7.39 83.81,7.39 83.93,7.52 83.93,10.06
GND on TOP: 53.58,12.6 53.58,3.58 55.49,3.58 55.49,12.6
GND on TOP: 41.9,13.1 52.06,13.1 52.18,13.23 52.18,14.37 51.93,14.63 41.9,14.63
GND on 02_GND: 42.3,1 42.3,7.5 41.71,8.91 40.3,9.5 9.3,9.5 9.3,19 8.71,20.41 7.3,21 1,21 1,59.22 2.78,61 90.3,61 90.3,3.2 88.1,1 ; 17 cut-outs
GND on 05_GND: 42.3,1 42.3,7.5 41.71,8.91 40.3,9.5 9.3,9.5 9.3,19 8.71,20.41 7.3,21 1,21 1,58.95 3.04,60.98 3.04,61 90.3,61 90.3,2.94 88.36,1 ; 17 cut-outs
GND on 09_GND: 42.3,1 42.3,7.5 41.71,8.91 40.3,9.5 9.3,9.5 9.3,19 8.71,20.41 7.3,21 1,21 1,58.95 3.04,60.98 3.04,61 90.3,61 90.3,2.94 88.36,1 ; 3 cut-outs
VDD_1.2V on TOP (solid shape): 12.19,24.47 12.31,24.47 12.31,24.15 13.32,24.15 14.47,23.01 14.47,22.76 13.88,22.76 13.88,22.77 12.51,22.77 12.51,22.76 9,22.76 9,25.93 12.19,25.93
VDD_1.2V on 04_SIG: 11.29,22.88 11.29,26.31 12.69,27.71 39.74,27.71 39.74,25.55 17.51,25.55 14.85,22.88
VDD_1.5V on TOP (solid shape): 12.56,13.49 10.27,13.49 10.27,17.04 12.56,17.04
VDD_1.5V on 07_SIG (solid shape): outline of 281 points within 10.4,13.49 17.13,20.34
VDD_1.5V on BOTTOM: 41.26,32.15 41.26,34.69 40.75,34.69 40.75,32.15
VDD_1.5V on 04_SIG: 41.52,34.95 41.52,32.15 41.39,32.03 40.25,32.03 40.25,29.74 42.91,27.07 42.91,22.25 42.41,21.74 22.85,21.74 21.32,20.22 21.32,15.52 19.29,13.49 10.78,13.49 10.27,13.99 10.27,16.79 10.53,17.04 16.75,17.04 19.04,19.33 19.04,21.87 21.96,24.79 39.1,24.79 40.12,25.8 40.12,27.71 38.72,29.11 37.2,29.11 37.2,35.08 41.39,35.08
VDD_1.8V on TOP (solid shape): 20.78,16.87 20.79,16.79 20.81,16.71 20.81,14.37 20.82,13.87 21.45,13.23 21.45,12.6 18.97,12.6 18.89,12.64 18.88,12.73 18.69,13.33 18.06,13.29 17.95,13.28 17.89,13.37 17.89,15.77 19.55,15.77 19.8,16.03 19.8,16.91 20.78,16.91
VDD_1.8V on 07_SIG (solid shape): outline of 288 points within 18.02,12.6 22.21,20.47
VDD_1.8V on BOTTOM: 70.22,54.89 69.33,54.89 69.33,58.82 69.08,59.08 48.5,59.08 48.5,57.43 47.74,57.43 47.74,58.32 47.61,58.44 46.98,58.44 46.47,57.94 46.34,57.94 45.2,59.08 40.75,59.08 40.63,58.95 8.75,58.95 8.5,58.7 8.5,57.17 2.78,51.46 2.78,22.88 1.13,22.88 1.13,53.36 8.75,60.98 69.46,60.98 70.22,60.22
VDD_1.8V on 03_SIG: 17.9,13.28 21.9,13.28 21.9,11.78 20.9,10.78 10.4,10.78 9.4,11.78 9.4,19.78 7.4,21.78 1.4,21.78 1.4,24.78 2.9,24.78 2.9,23.28 3.4,22.78 9.36,22.78 11.42,20.72 11.42,12.47 17.9,12.47
VDD_3.3V on TOP (solid shape): 23.1,28.09 23.1,24.08 22.85,24.08 22.85,23.89 22.75,23.58 22.85,23.28 22.85,23.26 22.09,22.5 20.94,22.5 20.43,23.01 21.07,23.65 21.07,24.28 21.45,24.28 21.45,24.24 21.58,24.24 21.58,24.28 22.21,24.28 22.21,26.06 20.95,26.06 20.95,26.17 20.69,26.17 20.69,28.47 22.72,28.47
VDD_3.3V on 06_PWR1: 20.94,21.49 20.94,27.33 33.01,27.33 33.01,26.69 33.52,26.69 33.52,27.33 35.67,27.33 35.67,26.82 36.18,26.82 36.18,27.33 38.34,27.33 38.34,26.82 38.72,26.82 38.72,27.33 42.02,27.33 42.02,48.79 47.23,48.79 47.23,47.63 47.72,47.14 48.07,47.14 48.25,46.96 48.25,41.86 46.22,39.83 46.22,24.03 47.36,22.88 47.36,21.49 35.8,21.49 35.8,21.61 32.75,21.61 32.75,21.49 29.71,21.49 29.71,21.74 29.2,21.74 29.2,21.49
VDD_5.0V on TOP (solid shape): 16.62,26.82 16.62,24.41 15.86,24.41 15.48,24.79 15.48,26.82 15.61,26.95 16.5,26.95
VDD_5.0V on TOP (solid shape): 17.28,18.8 17.39,18.7 17.39,17.4 16.77,16.79 16.12,16.79 16.12,17.8 16.88,18.57 16.88,18.82 17.28,18.82
VDD_5.0V on TOP (solid shape): 14.08,22.25 14.72,22.25 14.72,21.75 14.58,21.61 13.66,21.61 13.53,21.49 13.13,21.49 11.04,21.49 11.04,22.5 13.83,22.5
VDD_5.0V on TOP (solid shape): 19.6,18.92 19.63,19 19.7,19.03 19.73,19.02 20.06,19.02 20.78,18.31 20.78,17.55 19.55,17.55 19.55,18.83 19.6,18.83
VDD_5.0V on TOP (solid shape): 15.68,18.83 16.48,18.83 16.5,18.82 16.5,18.69 15.86,18.06 15.86,17.17 15.48,16.79 14.85,16.79 14.85,16.94 14.85,16.95 14.9,17.06 14.91,17.17 14.91,18.5 15.35,18.95 15.68,18.95
VDD_5.0V on TOP (solid shape): 18.97,25.8 18.97,24.92 18.53,24.92 18.15,25.09 17.77,24.93 17.75,24.92 17.63,24.92 17.61,24.93 17.35,25.08 17.04,25.05 17.01,25.04 16.88,25.17 16.88,25.8
VDD_5.0V on TOP: 61.58,10.82 61.58,3.71 59.17,3.71 59.17,10.82
VDD_5.0V on 06_PWR1: 42.3,1 42.3,7.5 41.71,8.91 40.3,9.5 31.1,9.5 31.1,11.45 14.59,11.45 14.59,14.12 11.04,14.12 11.04,22.3 10.58,22.76 6.97,22.76 6.97,27.33 20.69,27.33 20.69,21.23 32.75,21.23 32.75,21.11 35.8,21.11 35.8,21.23 37.96,21.23 37.96,20.34 38.21,20.34 38.47,20.6 38.98,20.6 38.98,20.98 40.25,20.98 40.25,21.23 44.56,21.23 44.56,15.72 47.43,12.85 77.58,12.85 77.58,6.5 82.41,6.5 82.41,10.06 90.3,10.06 90.3,3.07 88.23,1 ; 2 cut-outs
VDD_CORE on TOP (solid shape): 66.03,20.95 65.77,20.51 66.03,20.07 66.03,13.49 62.09,13.49 62.09,13.16 62.03,13.16 62.03,12.47 58.66,12.47 58.66,3.45 57.14,3.45 57.14,6.02 57.14,7.59 57.14,8.53 57.14,10.11 57.14,11.05 57.14,12.62 57.14,13.74 57.77,13.74 57.77,15.02 57.81,15.04 58.15,15.52 57.81,16 57.77,16.01 57.77,19.45 57.99,19.86 57.77,20.28 57.77,20.5 57.8,20.57 57.87,20.6 58.21,20.73 58.37,21.06 58.37,21.11 66.03,21.11
VDD_CORE on TOP: 48.76,16.41 42.02,16.41 42.02,17.93 44.69,17.93 44.69,20.09 46.09,20.09 46.22,19.96 46.22,17.93 48.76,17.93
VDD_CORE on 03_SIG: 42.66,35.58 50.53,35.58 51.17,34.95 51.17,31.01 50.79,30.63 45.83,30.63 45.33,31.14 45.33,31.39 45.07,31.65 42.91,31.65 42.41,32.03 42.41,35.33
VDD_CORE on 06_PWR1: 47.54,13.1 44.82,15.82 44.82,21.23 47.61,21.23 47.61,23.19 46.6,24.21 46.6,39.85 48.44,41.7 48.44,47.13 48.17,47.39 47.79,47.39 47.49,47.7 47.49,48.79 52.44,48.79 52.44,50.06 53.07,50.06 53.07,51.08 65.01,51.08 65.01,41.3 63.87,40.16 63.87,39.01 64.38,38.5 64.38,36.8 64.76,36.42 64.76,32.46 63.87,31.57 63.87,31.09 64.76,30.2 64.76,24.03 72.76,24.03 72.76,13.1
VDDA_DDR0_32A on 04_SIG: 63.9,47.78 63.9,44.28 65.9,42.28 65.9,40.15 64.53,38.78 55.9,38.78 55.9,36.78 67.4,36.78 67.4,46.78 66.4,47.78
VDDA_PCIE0 on 03_SIG: 62.98,51.08 58.28,51.08 58.28,51.59 56.5,51.59 56.5,48.54 63.61,48.54 63.61,49.3 64.25,49.3 65.14,50.19 65.14,50.32 65.65,50.82 65.65,54.13 65.14,54.63 63.23,54.63 62.98,54.38 62.98,52.73 63.36,52.35 63.36,51.46
VDDA_PLL on BOTTOM: 39.87,32.66 39.87,29.87 41.26,29.87 41.39,30 41.39,31.77 40.37,31.77 40.37,32.66
VDDA_PLL on 04_SIG: 65.4,41.78 56.88,41.78 56.88,47.78 54.72,47.78 54.72,40.78 45.9,40.78 45.9,31.78 40.5,31.78 40.5,29.78 49.4,29.78 49.4,39.28 64.39,39.28 65.4,40.29
VDDA_SERDES on 04_SIG: 57.52,47.01 57.52,48.03 49.64,48.03 49.64,50.57 58.41,50.57 58.41,47.01
(no net) on TOP: 21.07,17.17 21.07,14.63 22.34,14.63 22.34,17.04 21.58,17.04 21.45,17.17
(no net) on TOP: 14.08,19.71 14.08,17.55 12.81,17.55 12.56,17.8 11.8,17.8 11.8,18.95 13.07,18.95 13.83,19.71
(no net) on TOP: 20.82,17.55 20.82,18.31 20.05,19.07 19.55,19.07 19.55,17.55
(no net) on TOP: 14.72,21.74 14.72,22.25 14.08,22.25 13.83,22.5 11.04,22.5 11.04,21.49 14.47,21.49
(no net) on TOP: 57.14,3.45 57.14,13.74 57.77,13.74 57.77,21.11 66.03,21.11 66.03,13.49 62.09,13.49 62.09,12.47 58.66,12.47 58.66,3.45
(no net) on TOP: 17.51,13.49 15.48,13.49 15.48,16.03 15.8,16.34 16.69,16.34 17.77,17.42 17.77,16.41 17.51,16.15
(no net) on TOP: 17.39,18.82 17.39,17.3 16.88,16.79 16.12,16.79 16.12,17.8 16.88,18.57 16.88,18.82
(no net) on TOP: 18.4,26.06 19.93,26.06 19.93,28.47 18.4,28.47
(no net) on TOP: 14.59,25.8 14.59,24.15 14.21,23.77 14.08,23.77 13.07,24.79 12.56,24.79 12.56,25.8
(no net) on TOP: 15.32,21.52 16.74,21.52 16.74,20.72 16.75,20.72 18.5,20.72 18.52,20.74 18.52,21.52 20,21.52 20,21.7 18.52,21.7 18.52,22.5 18.51,22.51 16.74,22.51 16.74,22.5 16.74,21.7 15.32,21.7
(no net) on TOP: 13.96,13.49 15.1,13.49 15.1,16.15 14.59,16.66 14.59,17.17 14.34,17.42 13.96,17.04
(no net) on TOP: 19.04,24.92 17.13,24.92 16.88,25.17 16.88,25.8 19.04,25.8
(no net) on TOP: 21.58,18.31 21.58,17.55 23.74,17.55 23.74,18.31 23.23,18.31 22.85,18.69 21.96,18.69
(no net) on TOP: 16.62,24.41 16.62,26.82 16.5,26.95 15.61,26.95 15.48,26.82 15.48,24.79 15.86,24.41
(no net) on TOP: 14.85,25.8 15.23,25.8 15.23,27.46 9,27.46 9,26.44 14.21,26.44
(no net) on TOP: 15.48,16.79 15.86,17.17 15.86,18.06 16.5,18.69 16.5,18.82 16.37,18.95 15.35,18.95 14.85,18.44 14.85,16.79
(no net) on TOP: 18.28,18.31 18.28,16.15 19.16,16.15 19.16,18.31
(no net) on TOP: 20.94,20.72 20.94,20.22 22.09,19.07 23.99,19.07 23.99,17.17 23.36,17.17 23.36,15.01 23.61,14.76 24.88,14.76 24.88,20.22 23.23,20.22 22.72,20.72
(no net) on TOP: 14.47,22.76 14.47,23.01 13.32,24.15 12.31,24.15 12.31,25.93 9,25.93 9,22.76
(no net) on TOP: 12.56,17.04 12.56,13.49 10.27,13.49 10.27,17.04
(no net) on TOP: 20.82,16.91 20.82,13.87 21.45,13.23 21.45,12.6 17.89,12.6 17.89,15.77 19.55,15.77 19.8,16.03 19.8,16.91
(no net) on TOP: 20.43,23.01 21.07,23.65 21.07,24.28 22.21,24.28 22.21,26.06 20.69,26.06 20.69,28.47 22.72,28.47 23.1,28.09 23.1,23.52 22.09,22.5 20.94,22.5
(no net) on TOP: 19.93,24.15 20.56,24.15 20.56,24.41 21.07,24.92 21.83,24.92 21.83,25.8 19.8,25.8 19.8,24.79 19.93,24.66
(no net) on BOTTOM: 49.99,15.64 49.99,6.63 58.03,6.63 58.03,12.78 57.9,12.78 58.11,13 58.11,15.64 60.82,15.64 60.82,16.66 58.11,16.66 58.11,18.44 55.07,18.44 54.81,18.18 53.92,18.18 53.8,18.06 53.8,15.64
(no net) on BOTTOM: 52.53,22.76 52.53,20.34 51.51,20.34 51.51,18.95 53.67,18.95 53.8,18.82 58.11,18.82 58.11,22.76 ; 5 cut-outs
(no net) on BOTTOM: 46.3,13.99 46.3,17.55 46.43,17.42 47.19,17.42 47.32,17.55 47.32,18.18 53.42,18.18 53.42,16.03 49.73,16.03 49.73,13.99 ; 5 cut-outs
(no net) on BOTTOM: 65.9,16.41 65.9,17.55 66.03,17.42 66.79,17.42 66.92,17.55 66.92,18.18 73.01,18.18 73.01,16.03 69.33,16.03 69.33,13.87 67.04,13.87 67.04,16.41 ; 5 cut-outs
(no net) on BOTTOM: 69.58,15.64 69.58,14.12 66.92,14.12 66.92,16.53 63.36,16.53 63.36,15.64 65.77,15.64 65.77,13.99 63.23,13.99 62.22,12.98 62.22,6.75 64,4.98 69.08,4.98 69.08,5.99 68.82,6.25 68.82,10.18 71.87,13.23 75.93,13.23 80.25,8.91 86.73,8.91 87.87,10.06 87.87,12.47 87.62,12.72 83.05,12.72 82.41,13.36 82.41,14.76 77.71,14.76 77.71,18.44 74.66,18.44 74.41,18.18 73.52,18.18 73.39,18.06 73.39,15.64
(no net) on BOTTOM: 72.12,22.76 72.12,20.34 71.11,20.34 71.11,18.95 73.27,18.95 73.39,18.82 77.71,18.82 77.71,22.76 ; 5 cut-outs
(no net) on 07_SIG: 18.02,20.47 18.02,12.6 22.21,12.6 22.21,20.47
(no net) on 07_SIG: 10.4,13.49 10.4,19.45 14.85,19.45 15.74,20.34 16.88,20.34 17.13,20.09 17.13,14.76 15.86,13.49
11N1937 on TOP (solid shape): 17.77,16.41 17.51,16.15 17.51,13.49 15.48,13.49 15.48,16.03 15.8,16.34 16.69,16.34 17.59,17.25 17.77,17.25
11N1952 on TOP: 66.03,7.39 62.6,7.39 62.6,8.66 61.84,8.66 61.84,9.29 62.6,9.29 62.6,10.82 64.25,10.82 64.38,10.69 66.03,10.69 66.03,10.18 65.52,10.18 65.52,9.68 64.88,9.68 64.88,8.41 65.52,8.41 65.52,7.9 66.03,7.9
11N1968 on TOP (solid shape): 14.59,17.17 14.59,16.53 14.72,16.53 15.1,16.15 15.1,13.49 13.96,13.49 13.96,17.04 14.16,17.25 14.4,17.25 14.4,17.27 14.46,17.3
11N1970 on TOP (solid shape): 12.5,27.46 12.97,27.35 13.44,27.46 15.23,27.46 15.23,25.98 15.04,25.98 15.04,25.8 14.91,25.8 14.91,25.98 14.85,25.98 14.85,26.06 14.59,26.06 14.21,26.44 9,26.44 9,27.46
11N1971 on TOP (solid shape): 21.58,17.04 22.34,17.04 22.34,14.63 21.07,14.63 21.07,15.94 21.08,15.94 21.08,17.17 21.45,17.17
11N2253 on TOP: 86.86,12.47 83.55,12.47 83.55,11.71 82.66,11.71 82.66,10.82 81.14,10.82 81.14,13.49 82.54,13.49 82.66,13.61 82.66,14.25 86.86,14.25
11N2296 on TOP (solid shape): 19.93,26.17 19.48,26.17 19.48,26.06 19.35,26.06 19.35,26.17 18.4,26.17 18.4,28.47 19.93,28.47
DDR_1.8V on TOP (solid shape): 22.87,20.58 22.87,20.56 23,20.37 23.19,20.24 23.21,20.24 23.23,20.22 24.79,20.22 24.79,18.29 24.88,18.29 24.88,17.32 24.79,17.32 24.79,15.44 24.88,15.44 24.88,14.76 23.61,14.76 23.36,15.01 23.36,17.16 24.04,17.16 24.04,18.63 23.99,18.63 23.99,19.07 22.17,19.07 21.17,20.07 21.08,20.14 20.96,20.19 20.94,20.22 20.94,20.61 22.83,20.61
DDR_1.8V on 04_SIG: 23.74,16.41 56.12,16.41 59.8,20.09 59.8,36.6 56.4,36.6 56.4,22.15 53.07,18.82 36.18,18.82 34.79,20.22 28.05,20.22 26.66,18.82 25.9,18.82 24.37,20.34 22.09,20.34 22.09,18.06
DDR_VDDQ on TOP: 79.11,6.75 79.11,10.18 77.58,11.71 77.58,12.98 79.87,12.98 79.87,11.45 80.51,10.82 80.51,8.41 81.27,8.41 81.27,6.75
DDR_VDDQ on 06_PWR1: 77.84,6.75 77.84,13.1 73.01,13.1 73.01,24.28 65.01,24.28 65.01,30.3 64.12,31.19 64.12,31.47 65.01,32.36 65.01,36.53 64.63,36.91 64.63,38.63 64.12,39.14 64.12,42.26 65.27,43.41 65.27,55.76 67.95,55.76 67.95,61 90.3,61 90.3,36.98 90.28,36.98 90.28,20.17 79.49,20.17 79.49,15.14 90.3,15.14 90.3,10.31 82.16,10.31 82.16,6.75
DDR_VTT on TOP: outline of 122 points within 80.51,15.64 90.16,37.62
DDR_VTT on TOP: 82.03,17.55 82.54,17.04 82.54,16.66 82.28,16.41 82.28,15.52 78.73,15.52 78.73,17.17 79.11,17.55
DDR_VTT on BOTTOM: 82.28,15.52 78.85,15.52 78.85,16.41 78.6,16.66 78.6,17.68 81.9,17.68 82.54,17.04 82.54,16.53 82.28,16.28
DDR_VTT on 06_PWR1: 79.74,15.39 79.74,19.84 90.3,19.84 90.3,15.39
EXT_3.3V on 04_SIG: 12.31,13.1 13.58,13.1 14.59,12.09 35.55,12.09 36.31,11.33 56.88,11.33 58.41,9.8 65.52,9.8 65.52,12.6 66.03,13.1 68.06,13.1 68.44,12.72 68.44,4.09 69.08,3.45 77.71,3.45 88.76,14.5 88.76,20.09 87.87,20.98 84.44,20.98 84.32,21.11 84.32,21.74 84.7,22.12 89.78,22.12 90.28,21.61 90.28,8.66 83.05,1.42 43.93,1.42 43.29,2.06 43.29,8.41 41.9,9.8 31.74,9.8 31.48,9.55 29.45,9.55 28.69,10.31 12.94,10.31 12.31,10.95
EXT_3.3V on 06_PWR1: 9.3,9.5 9.3,19 8.71,20.41 7.3,21 1,21 1,58.57 3.42,60.99 3.42,61 67.67,61 67.68,60.99 67.68,56.05 65.01,56.05 65.01,51.33 52.82,51.33 52.82,50.32 52.18,50.32 52.18,49.34 51.89,49.05 41.77,49.05 41.77,27.58 35.42,27.58 35.42,28.09 34.79,28.09 34.79,27.58 34.4,27.58 34.15,28.42 33.9,27.58 6.72,27.58 6.72,22.5 10.48,22.5 10.78,22.2 10.78,13.87 14.34,13.87 14.34,11.2 30.85,11.2 30.85,9.5 ; 17 cut-outs
EXT_12.0V on BOTTOM (solid shape): 77.71,18.82 74.59,18.82 74.59,18.83 73.38,18.83 73.27,18.95 71.11,18.95 71.11,19.06 74.29,19.06 74.29,19.3 73.57,19.3 73.57,19.06 71.11,19.06 71.11,19.54 74.28,19.54 74.28,19.81 73.56,19.81 73.56,19.54 71.11,19.54 71.11,20.05 74.27,20.05 74.27,20.29 73.59,20.29 73.59,20.05 71.11,20.05 71.11,20.22 71.11,20.23 71.11,20.34 72.12,20.34 72.12,20.47 72.12,20.72 72.63,20.72 72.63,20.79 73.1,20.79 73.1,21.5 72.82,21.5 72.82,20.79 72.63,20.79 72.63,21.49 72.38,21.49 72.38,20.72 72.12,20.72 72.12,21.41 72.45,21.73 72.45,21.75 72.5,21.8 72.5,22.3 74.79,22.3 74.82,22.3 74.87,22.31 74.91,22.33 74.96,22.35 75,22.38 75.02,22.39 75.05,22.39 75.13,22.38 75.2,22.38 75.27,22.38 75.34,22.4 75.41,22.42 75.48,22.46 75.54,22.5 75.6,22.54 75.65,22.59 75.7,22.65 75.72,22.68 77.5,22.68 77.58,22.76 77.71,22.76
EXT_12.0V on BOTTOM (solid shape): outline of 170 points within 51.51,18.82 58.11,22.76
EXT_12.0V on TOP: 67.04,7.9 67.04,7.01 67.42,7.01 67.42,6.5 66.92,6.5 66.92,3.33 64.63,3.33 64.63,7.14 66.28,7.14 66.28,7.9
EXT_12.0V on TOP: 8.75,44.6 1.51,44.6 1.51,31.65 4.81,28.34 8.62,28.34 8.75,28.47 8.75,32.03 8.62,32.15 6.59,32.15 3.42,35.33 3.42,43.2 8.75,43.2
EXT_12.0V on TOP: 86.22,10.06 84.19,10.06 84.19,7.26 83.3,6.37 81.78,6.37 81.78,3.33 84.32,3.33 87.49,6.5 90.28,6.5 90.28,7.9 86.86,7.9 86.86,8.66 86.22,8.66
EXT_12.0V on 03_SIG: 21.96,33.04 21.96,25.8 25.01,22.76 88.13,22.76 90.03,20.85 90.03,5.74 88.76,4.47 68.31,4.47 67.3,3.45 65.9,3.45 64.88,4.47 44.95,4.47 43.29,6.12 43.29,9.42 41.26,11.45 25.01,11.45 21.96,14.5 19.16,14.5 18.28,15.39 13.07,15.39 11.67,16.79 11.67,23.77 6.72,28.73 6.72,32.66 7.86,33.81 21.2,33.81
L_1_CORE_PHASE on BOTTOM (solid shape): 73.01,16.03 69.33,16.03 69.33,13.87 67.04,13.87 67.04,14.89 69.11,14.89 69.11,15.59 68.81,15.59 68.81,14.89 67.04,14.89 67.04,15.97 68.38,15.97 68.38,16.31 67.7,16.31 67.7,15.97 67.04,15.97 67.04,16.41 65.9,16.41 65.9,16.55 68.37,16.55 68.37,16.84 67.71,16.84 67.71,16.55 65.9,16.55 65.9,17.07 68.37,17.07 68.37,17.32 67.72,17.32 67.72,17.07 65.9,17.07 65.9,17.43 65.91,17.46 65.92,17.47 65.94,17.48 65.96,17.48 66.03,17.42 66.79,17.42 66.92,17.55 66.92,17.56 68.39,17.56 68.39,17.82 67.69,17.82 67.69,17.56 66.92,17.56 66.92,17.85 66.92,17.87 66.94,17.9 66.96,17.92 66.99,17.93 67.02,17.93 67.06,17.93 67.12,17.93 67.18,17.93 67.24,17.94 67.3,17.96 67.35,17.99 67.41,18.02 67.43,18.04 68.69,18.04 68.69,18.18 73.01,18.18
L_1_CORE_PHASE on TOP: 68.82,18.44 68.82,17.68 70.98,17.68 70.98,16.91 68.82,16.91 68.82,16.03 73.65,16.03 73.65,18.44
L_2_CORE_PHASE on BOTTOM (solid shape): 53.42,16.03 49.73,16.03 49.73,13.99 46.3,13.99 46.3,14.89 49.52,14.89 49.52,15.59 49.21,15.59 49.21,14.89 46.3,14.89 46.3,15.97 48.78,15.97 48.78,16.31 48.11,16.31 48.11,15.97 46.3,15.97 46.3,16.55 48.77,16.55 48.77,16.84 48.12,16.84 48.12,16.55 46.3,16.55 46.3,17.07 48.77,17.07 48.77,17.32 48.13,17.32 48.13,17.07 46.3,17.07 46.3,17.43 46.31,17.46 46.33,17.47 46.34,17.48 46.36,17.48 46.43,17.42 47.19,17.42 47.32,17.55 47.32,17.56 48.79,17.56 48.79,17.82 48.1,17.82 48.1,17.56 47.32,17.56 47.32,17.85 47.33,17.87 47.34,17.9 47.37,17.92 47.39,17.93 47.42,17.93 47.47,17.93 47.53,17.93 47.59,17.93 47.65,17.94 47.7,17.96 47.76,17.99 47.81,18.02 47.83,18.04 49.1,18.04 49.1,18.18 53.42,18.18
L_2_CORE_PHASE on TOP: 53.58,16.15 53.58,16.91 52.69,16.91 52.69,17.68 53.58,17.68 53.58,18.44 49.26,18.44 49.26,16.15
MAIN_3.3V on 04_SIG: 15.74,31.39 17.64,31.39 17.64,33.04 15.74,33.04
MH_1 on TOP, BOTTOM: 69.1,8 78.6,8
MH_2 on TOP, BOTTOM: 31.56,43.99 41.06,43.99

Small or netless copper shapes (teardrops, artwork), in the pictures only: 8 on TOP

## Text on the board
Ref Des/Silkscreen Bottom: PCBD0082-001 REV 01
User.Comments: 978-600-1333 X 212 | PCBD0082-001 | HELIUM BOARD
Ref Des/Silkscreen Top: S/N LABEL
PAGE_OUTLINE: K2 ENGINEERING | G | F | E | 10 | 9 | 8
DIMENSION: EDGE OF BOARD | BREAKAWAY DETAIL | SCALE: NONE | 0.150 | 0.120 | 0.030 NPTH | 0.062 ROUTE | NOTE 19. ALL 10.1 MIL AND 8.1 MIL VIAS | SEE VIAFILL.ART AND | SEE BREAKAWAY DETAIL | SEE NOTE 19
BODY_CENTER: 4/1 | SHEET 1 OF 1 | HELIUM BOARD
User.7: LAYER 1 | 01_TOP | COMP | SIDE
User.8: 02_PLANE | LAYER 2 | PLANE
User.9: LAYER 3 | SIGNAL | 03_SIGNAL
User.10: LAYER 4 | 04_SIGNAL | SIGNAL
User.11: LAYER 5 | 05_PLANE | PLANE
User.12: LAYER 6 | 06_PLANE | PLANE
User.13: LAYER 7 | 07_SIGNAL | SIGNAL
User.14: LAYER 8 | 08_SIGNAL | SIGNAL
User.15: LAYER 9 | 09_PLANE | PLANE
User.16: LAYER 10 | 10_BOTTOM | BOTTOM
User.17: LAYER 11 | 11_PLANE | PLANE
User.18: 12_SIGNAL | LAYER 12 | SIGNAL
User.19: LAYER 13 | 13_PLANE | PLANE
User.20: SIGNAL | LAYER 14 | 14_BOTTOM
User.21: LAYER 15 | SIGNAL | 15_SIGNAL
User.22: LAYER 16 | 16_PLANE | PLANE
User.23: PRIMARY SIDE SOLDER PASTE
User.24: SECONDARY SIDE SOLDER PASTE
User.25: SECONDARY SIDE SILKSCREEN
User.26: PRIMARY SIDE SILKSCREEN
User.27: SECONDARY SIDE SOLDERMASK
User.28: PRIMARY SIDE SOLDERMASK
User.29: LAYER 17 | 17_PLANE | PLANE
User.30: LAYER 8 | 8_BOTTOM | SOLDER | SIDE
User.31: 2/1 | SHEET 27 | ASSEMBLY DRAWING SECONDARY SIDE | ASSEMBLY DRAWING | 4X10 SFP+ MODULE
User.32: LAYER 19 | 19_PWR3_3V.art | PLANE
User.33: LAYER 20 | 20_BOTTOM.art | SOLDER | SIDE
User.34: PCBD0082-001
User.35: BOARD OUTLINE
User.36: VIAFILL
